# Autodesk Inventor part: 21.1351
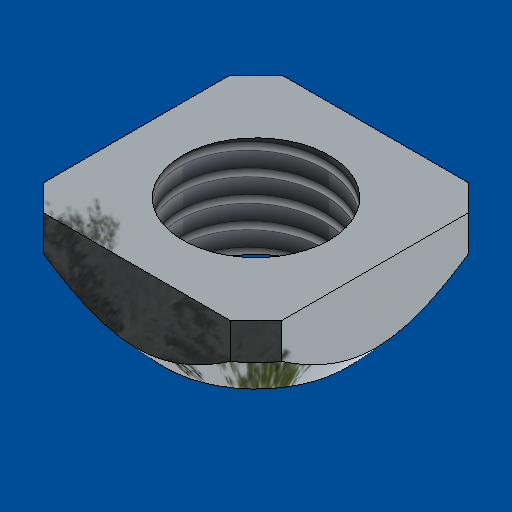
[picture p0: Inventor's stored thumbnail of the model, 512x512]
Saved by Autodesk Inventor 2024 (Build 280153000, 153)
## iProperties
Created: 2006-12
Part Number: 21.1351
Document SubType Name: Modeling
Designer: Andy Moles
Material: Steel, Mild
Mass: 3.98636 g
Surface Area: 5.54896 cm^2
Volume: 0.507817 cm^3
Density: 7.85 g/cm^3
Description: M8 SQUARE NUT
Vendor: S
Appearance: Zinc
Author: Andy Moles
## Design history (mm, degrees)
sketch "Sketch2"
  geometry: L1 (-5.086, -6.5)-(5.086, -6.5); L2 (6.5, -5.086)-(6.5, 5.086); L3 (5.086, 6.5)-(-5.086, 6.5); L4 (-6.5, 5.086)-(-6.5, -5.086); L5 (-6.5, 6.5)-(6.5, -6.5); L6 (5.086, 6.5)-(6.5, 5.086); L7 (0, -6.5)-(0, 6.5); L8 (-6.5, 0)-(6.5, 0); L9 (-5.086, 6.5)-(-6.5, 5.086); L10 (-5.086, -6.5)-(-6.5, -5.086); L11 (5.086, -6.5)-(6.5, -5.086); C1 r 4 at (0, 0); 2 further points
  constraints: 22 end point, 6 symmetric about line, 4 parallel, 3 midpoint, 2 coincident, 2 perpendicular, 1 centre point, 1 horizontal
  dimensions: "THREAD" = 8 diameter of C1; "d3" = 45 deg angle of L3 L6 (derived); "d4" = 2 distance of L3.start L2.end
extrude "Extrusion1" new body sketch "Sketch2" distance "d5" = 5.5; taper "d6" = 0 deg
workplane "Work Plane1"
sketch "Sketch4"
  geometry: L1 (12.192, 0)-(4.192, 0) reference; L2 (8.192, 0)-(13.192, 0); L3 (16.385, 5.5)-(16.385, 3.5); L4 (13.192, 0)-(16.797, 3.952); L5 (13.192, 0)-(16.385, 0); L6 (16.385, 3.5)-(16.385, 0); L7 (16.797, 3.952)-(16.797, -0.412); L8 (16.797, -0.412)-(13.192, -0.412); L9 (13.192, -0.412)-(13.192, 0); L10 (8.192, 5.5)-(8.192, 0); L11 (16.385, 5.5)-(16.385, 0) reference; L12 (16.385, 3.5)-(17.502, 3.5); L13 (9.192, 5.5)-(16.385, 5.5) reference
  constraints: 20 end point, 6 perpendicular, 1 collinear, 1 midpoint, 1 parallel, 1 point on line
  dimensions: "d10" = 5 distance of L2.start L2.end; "d15" = 2 distance between parallel lines of L12 L13
revolve "Revolution1" sketch "Sketch4" stored, may be unused: angle "d12" = 90 deg
thread "Thread1" dims "d13" = 10, "d14" = 0
body "Solid1"
